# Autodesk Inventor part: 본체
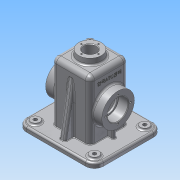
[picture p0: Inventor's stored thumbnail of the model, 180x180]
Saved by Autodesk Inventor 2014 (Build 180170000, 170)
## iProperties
Created: 2015-12
Part Number: 본체
Material: 알루미늄 6061
Document SubType Name: Modeling
Designer: Administrator
Density: 2.71 g/cm^3
Appearance: 알루미늄 - 평지
Author: Administrator
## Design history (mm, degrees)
sketch "스케치2"
  geometry: L1 (60, 52.5)-(-60, 52.5); L2 (-60, 52.5)-(-60, -52.5); L3 (-60, -52.5)-(60, -52.5); L4 (60, -52.5)-(60, 52.5); L5 (60, 52.5)-(-60, -52.5); L6 (-60, 52.5)-(60, -52.5); 1 further point
  constraints: 12 end point, 2 midpoint, 2 parallel, 1 horizontal, 1 perpendicular
  dimensions: "d2" = 120 distance of L3.end L2.end; "d3" = 105 distance of L2.end L1.end
extrude "돌출1" new body sketch "스케치2" distance "d4" = 2; taper "d5" = 0 deg
sketch "스케치3"
  geometry: L1 (65, 57.5)-(-65, 57.5); L2 (-65, 57.5)-(-65, -57.5); L3 (-65, -57.5)-(65, -57.5); L4 (65, -57.5)-(65, 57.5); L5 (65, 57.5)-(-65, -57.5); L6 (-65, 57.5)-(65, -57.5); 1 further point
  constraints: 12 end point, 2 midpoint, 2 parallel, 1 horizontal, 1 perpendicular
  dimensions: "d6" = 130 distance of L3.end L2.end; "d7" = 115 distance of L2.end L1.end
extrude "돌출2" join sketch "스케치3" distance "d8" = 8; taper "d9" = 0 deg
fillet "모깎기1" dims "d10" = 10
fillet "모깎기2" dims "d11" = 15
sketch "스케치5"
  geometry: L1 (32.5, 32.5)-(-32.5, 32.5); L2 (-32.5, 32.5)-(-32.5, -32.5); L3 (-32.5, -32.5)-(32.5, -32.5); L4 (32.5, -32.5)-(32.5, 32.5); L5 (32.5, 32.5)-(-32.5, -32.5); L6 (-32.5, 32.5)-(32.5, -32.5); 1 further point
  constraints: 12 end point, 2 midpoint, 2 parallel, 1 horizontal, 1 perpendicular
  dimensions: "d12" = 65 distance of L3.end L2.end; "d13" = 65 distance of L2.end L1.end
extrude "돌출3" join sketch "스케치5" distance "d14" = 100; taper "d15" = 0 deg
sketch "스케치6"
  geometry: L1 (42.5, 0)-(-42.5, 0) reference; C1 r 27.5 at (0, 55); 2 further points
  constraints: 1 centre point, 1 midpoint, 1 vertical alignment
  dimensions: "d16" = 55 diameter of C1; "d17" = 55 distance from line of L1 C1.centre
extrude "돌출4" join sketch "스케치6" stored distance "d18" = 95; taper "d19" = 0 deg
hole "구멍1" diameter "d22" = 30; stored, may be unused: countersink angle "d26" = 90 deg, drill point angle "d28" = 0 deg; dims "d20" = 10, "d21" = 10, "d23" = 6, "d24" = 35, "d25" = 17, "d27" = 57
fillet "모깎기3" dims "d29" = 8
fillet "모깎기4" dims "d30" = 8
sketch "스케치7"
  geometry: C1 r 20 at (0, 0); 1 further point
  constraints: 1 centre point, 1 coincident
  dimensions: "d31" = 40 diameter of C1
extrude "돌출5" join sketch "스케치7" distance "d32" = 10; taper "d33" = -5 deg
sketch "스케치8"
  geometry: L1 (27.5, 27.5)-(-27.5, 27.5); L2 (-27.5, 27.5)-(-27.5, -27.5); L3 (-27.5, -27.5)-(27.5, -27.5); L4 (27.5, -27.5)-(27.5, 27.5); L5 (27.5, 27.5)-(-27.5, -27.5); L6 (-27.5, 27.5)-(27.5, -27.5); 1 further point
  constraints: 12 end point, 2 midpoint, 2 parallel, 1 horizontal, 1 perpendicular
  dimensions: "d34" = 55 distance of L3.end L2.end; "d35" = 55 distance of L2.end L1.end
extrude "돌출6" cut sketch "스케치8" distance "d36" = 105; taper "d37" = 0 deg
fillet "모깎기9" dims "d98" = 3
fillet "모깎기6" dims "d95" = 3
hole "구멍2" diameter "d40" = 21; stored, may be unused: countersink angle "d44" = 90 deg, drill point angle "d46" = 0 deg; dims "d38" = 10, "d39" = 10, "d41" = 6, "d42" = 35, "d43" = 17, "d45" = 50
sketch "스케치10"
  geometry: L1 (-32.5, 10)-(-32.5, 102) reference; L2 (-57.5, 10)-(-42.5, 10) reference; L3 (42.5, 10)-(-42.5, 10) reference; L4 (42.5, 10)-(57.5, 10) reference; L5 (32.5, 102)-(32.5, 10) reference; L6 (47.5, 10)-(32.5, 95.069); L7 (57.5, 10)-(57.5, 2) reference; 4 further points
  constraints: 2 end point, 2 point on line
  dimensions: "d47" = 10 deg angle of L7 L6; "d48" = 10 horizontal distance of L7.end L6.start
feature "리브1" sketch "스케치10" dims "d49" = 1, "d50" = 10, "d51" = 0, "d52" = 0, "d53" = 1, "d54" = 1
sketch "스케치11"
  geometry: L1 (0, 0)-(-21, 0); C1 r 27.5 at (0, 0) reference; 2 further points
  constraints: 2 end point, 1 coincident, 1 horizontal
  dimensions: "d55" = 21 distance of L1.start L1.end
hole "구멍3" sketch "스케치11" at (-21, 0) diameter "d56" = 3.242; stored, may be unused: countersink angle "d60" = 90 deg, drill point angle "d62" = 118 deg; dims "d57" = 8, "d58" = 35, "d59" = 17, "d61" = 10
sketch "스케치13"
  geometry: L1 (0, 0)-(0, 14.5); C1 r 10.5 at (0, 0) reference; 1 further point
  constraints: 2 end point, 1 coincident, 1 vertical
  dimensions: "d66" = 14.5 distance of L1.start L1.end
hole "구멍4" sketch "스케치13" at (0, 14.5) diameter "d67" = 2.459; stored, may be unused: countersink angle "d71" = 90 deg, drill point angle "d73" = 118 deg; dims "d68" = 7, "d69" = 35, "d70" = 17, "d72" = 9
sketch "스케치14"
  geometry: C1 r 7.5 at (-50, 42.5); C2 r 7.5 at (50, 42.5); C3 r 7.5 at (-50, -42.5); C4 r 7.5 at (50, -42.5); A1 r 15 centre (-50, 42.5) between (-50, 57.5) and (-65, 42.5) reference; A2 r 15 centre (-50, -42.5) between (-65, -42.5) and (-50, -57.5) reference; A3 r 15 centre (50, -42.5) between (50, -57.5) and (65, -42.5) reference; A4 r 15 centre (50, 42.5) between (65, 42.5) and (50, 57.5) reference; 1 further point
  constraints: 4 centre point, 4 coincident
  dimensions: "d77" = 15 diameter of C1; "d78" = 15 diameter of C2; "d79" = 15 diameter of C3; "d80" = 15 diameter of C4
extrude "돌출7" join sketch "스케치14" distance "d81" = 3; taper "d82" = 0 deg
sketch "스케치15"
  geometry: C1 r 7.5 at (0, 0) reference; C2 r 7.5 at (-100, 0) reference; C3 r 7.5 at (-100, -85) reference; C4 r 7.5 at (0, -85) reference; 5 further points
  constraints: 4 coincident
hole "구멍5" sketch "스케치15" at (-100, 0), (-100, -85), (0, -85), (0, 0) diameter "d83" = 6; stored, may be unused: countersink angle "d87" = 90 deg, drill point angle "d89" = 0 deg; dims "d84" = 6, "d85" = 4, "d86" = 2, "d88" = 8
fillet "모깎기8" dims "d97" = 3
sketch "스케치18"
  geometry: L1 (-35.5, 27.5)-(-47.5, 27.5) reference; L2 (-32.5, 10)-(-32.5, 102) reference; L3 (-50, 10)-(50, 10) reference; L4 (47.5, 27.5)-(35.5, 27.5) reference; L5 (27.5, 0)-(27.5, 102) reference; L6 (-27.5, 102)-(-27.5, 0) reference; L7 (-42.5, 10)-(-42.5, 27.5); L8 (-27.5, 27.5)-(-27.5, 10); L9 (-42.5, 10)-(-27.5, 10); L10 (-27.5, 27.5)-(-42.5, 27.5); L11 (42.5, 27.5)-(42.5, 10); L12 (27.5, 10)-(42.5, 10); L13 (42.5, 27.5)-(27.5, 27.5); L14 (27.5, 27.5)-(27.5, 10); 2 further points
  constraints: 16 end point, 10 point on line, 3 collinear, 3 parallel, 1 perpendicular
  dimensions: "d100" = 15 distance between parallel lines of L7 L8; "d101" = 15 distance between parallel lines of L14 L11
extrude "돌출9" join sketch "스케치18" stored distance "d102" = 6; taper "d103" = 0 deg
chamfer "모따기1" distance "d104" = 1; stored, may be unused: second distance "d105" = 2, angle "d106" = 45 deg
fillet "모깎기10" dims "d107" = 3
fillet "모깎기11" dims "d108" = 3
fillet "모깎기12" dims "d109" = 3
fillet "모깎기13" dims "d110" = 1
sketch "스케치19"
  geometry: L1 (-18, 5.375)-(-18, 43.625) reference; L2 (0, -8)-(91, -8) reference; A1 r 30.5 centre (47, 24.5) between (28.834, 49) and (28.834, 0) reference; 2 further points
  constraints: 1 horizontal alignment, 1 other
  dimensions: "d111" = 26 distance from line of L1 point (8, 24.5); "d114" = 32.5 distance from line of L2 point (8, 24.5) (derived)
feature "엠보싱1" sketch "스케치19" dims "d112" = 0.5, "d113" = 0
fillet "모깎기14" dims "d115" = 0.3
node "솔리드1"
mirror "대칭1"
mirror "대칭2"
pattern_circular "원형 패턴1" dims angle "d64" = 360 deg
mirror "대칭3"
pattern_circular "원형 패턴2" dims angle "d75" = 360 deg
node "투영된 루프1"
node "투영된 루프2"
node "투영된 루프3"
